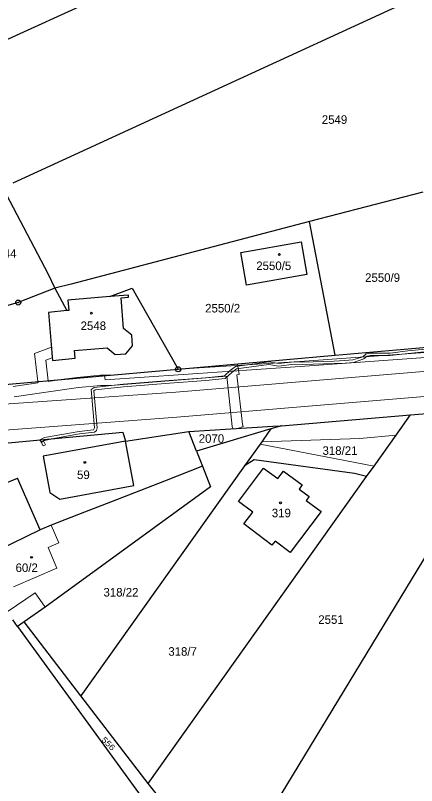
# Model space of a CAD drawing. Extents: x -606517 to -602431, y -1183120 to -1179397.
# Drawn here: x -605212.1 to -605132.4, y -1181010.4 to -1180857.3 of the extents above; entities that cross this region are included whole.
import ezdxf
from ezdxf.enums import TextEntityAlignment as Align

# ---------------------------------------------------------------- set-up
doc = ezdxf.new("R2010")
doc.units = 0
doc.header["$LTSCALE"] = 0.68
for name, color, linetype, lineweight in [('1', 7, 'Continuous', 25), ('13', 7, 'Continuous', 13), ('4', 7, 'Continuous', 13), ('5', 7, 'Continuous', 25), ('8', 7, 'Continuous', 25)]:
    doc.layers.add(name, color=color, linetype=linetype, lineweight=lineweight)
doc.layers.add('2', color=7, linetype='Continuous')

msp = doc.modelspace()

# ---------------------------------------------------------------- linework, layer by layer
at = {"layer": '1'}
for p, q in [((-605226.86, -1180868.06), (-605115.13, -1180816.68)), ((-605212.57, -1180890.57), (-605101.48, -1180839.48)), ((-605214.61, -1180891.56), (-605205.72, -1180908.62)), ((-605131.18, -1180892.4), (-605153.68, -1180898.29)), ((-605153.68, -1180898.29), (-605201.05, -1180910.69)), ((-605148.55, -1180924.86), (-605153.68, -1180898.29)), ((-605167.33, -1180904.4), (-605155.36, -1180902.31)), ((-605155.36, -1180902.31), (-605154.22, -1180908.81)), ((-605166.2, -1180910.91), (-605167.33, -1180904.4)), ((-605205.72, -1180908.62), (-605204.32, -1180911.54)), ((-605154.22, -1180908.81), (-605166.2, -1180910.91)), ((-605204.32, -1180911.54), (-605211.57, -1180914.37)), ((-605201.05, -1180910.69), (-605204.32, -1180911.54)), ((-605204.32, -1180911.54), (-605201.94, -1180915.98)), ((-605193.36, -1180913.2), (-605188.96, -1180911.53)), ((-605188.96, -1180911.53), (-605179.81, -1180927.64)), ((-605193.36, -1180913.2), (-605201.72, -1180913.89)), ((-605189.68, -1180912.89), (-605193.36, -1180913.2)), ((-605191.14, -1180913.46), (-605189.64, -1180913.33)), ((-605189.64, -1180913.33), (-605189.68, -1180912.89)), ((-605211.57, -1180914.37), (-605221.79, -1180917.3)), ((-605201.72, -1180913.89), (-605201.55, -1180915.94)), ((-605190.63, -1180919.53), (-605191.14, -1180913.46)), ((-605201.94, -1180915.98), (-605205.58, -1180916.34)), ((-605205.58, -1180916.34), (-605204.76, -1180925.9)), ((-605201.55, -1180915.94), (-605201.94, -1180915.98)), ((-605189.01, -1180920.85), (-605190.63, -1180919.53)), ((-605188.84, -1180922.97), (-605189.01, -1180920.85)), ((-605200.41, -1180923.92), (-605193.9, -1180923.39)), ((-605200.29, -1180925.46), (-605200.41, -1180923.92)), ((-605193.9, -1180923.39), (-605192.29, -1180924.72)), ((-605190.21, -1180924.54), (-605188.84, -1180922.97)), ((-605148.55, -1180924.86), (-605124.32, -1180922.7)), ((-605204.76, -1180925.9), (-605200.29, -1180925.46)), ((-605192.29, -1180924.72), (-605190.21, -1180924.54)), ((-605179.81, -1180927.64), (-605148.55, -1180924.86)), ((-605226.72, -1180931.78), (-605179.81, -1180927.64)), ((-605133.61, -1180936.72), (-605112.56, -1180934.97)), ((-605159.22, -1180938.85), (-605133.61, -1180936.72)), ((-605136.46, -1180940.72), (-605133.61, -1180936.72)), ((-605177.65, -1180940.02), (-605160.98, -1180938.96)), ((-605159.22, -1180938.85), (-605161.36, -1180939.5)), ((-605160.98, -1180938.96), (-605159.22, -1180938.85)), ((-605228.62, -1180943.64), (-605190.82, -1180940.16)), ((-605190.82, -1180940.16), (-605190.27, -1180941.9)), ((-605190.27, -1180941.9), (-605177.65, -1180940.02)), ((-605176.13, -1180943.95), (-605177.65, -1180940.02)), ((-605161.36, -1180939.5), (-605176.13, -1180943.95)), ((-605161.89, -1180940.23), (-605163.17, -1180942.04)), ((-605161.36, -1180939.5), (-605161.89, -1180940.23)), ((-605140.84, -1180946.88), (-605136.46, -1180940.72)), ((-605190.27, -1180941.9), (-605206.62, -1180944.94)), ((-605163.5, -1180942.5), (-605166.58, -1180946.83)), ((-605163.17, -1180942.04), (-605163.5, -1180942.5)), ((-605176.13, -1180943.95), (-605174.98, -1180946.91)), ((-605166.58, -1180946.83), (-605199.13, -1180992.55)), ((-605174.98, -1180946.91), (-605182.52, -1180949.87)), ((-605174.98, -1180946.91), (-605173.38, -1180951.02)), ((-605164.7, -1180945.67), (-605166.58, -1180946.83)), ((-605144.74, -1180948.36), (-605164.7, -1180945.67)), ((-605142.34, -1180948.98), (-605140.84, -1180946.88)), ((-605167.8, -1180953.9), (-605162.8, -1180947.3)), ((-605162.8, -1180947.3), (-605159.99, -1180949.35)), ((-605159.99, -1180949.35), (-605158.84, -1180947.87)), ((-605158.84, -1180947.87), (-605155.13, -1180950.61)), ((-605142.34, -1180948.98), (-605144.74, -1180948.36)), ((-605221.47, -1180953.43), (-605211.76, -1180949.26)), ((-605207.23, -1180959.55), (-605211.76, -1180949.26)), ((-605182.52, -1180949.87), (-605193.25, -1180954.05)), ((-605185.78, -1181010.01), (-605142.34, -1180948.98)), ((-605173.38, -1180951.02), (-605206.24, -1180974.94)), ((-605155.13, -1180950.61), (-605155.76, -1180951.46)), ((-605155.76, -1180951.46), (-605153.75, -1180952.94)), ((-605153.75, -1180952.94), (-605154.32, -1180953.71)), ((-605193.25, -1180954.05), (-605198.4, -1180956.04)), ((-605164.97, -1180956.02), (-605167.8, -1180953.9)), ((-605154.32, -1180953.71), (-605151.38, -1180955.91)), ((-605198.4, -1180956.04), (-605205.06, -1180958.6)), ((-605166.74, -1180958.37), (-605164.97, -1180956.02)), ((-605151.38, -1180955.91), (-605157.55, -1180964.07)), ((-605205.06, -1180958.6), (-605207.23, -1180959.55)), ((-605161.15, -1180962.6), (-605166.74, -1180958.37)), ((-605207.23, -1180959.55), (-605219.08, -1180965.25)), ((-605128.32, -1180960.97), (-605169.43, -1181028.73)), ((-605160.54, -1180961.8), (-605161.15, -1180962.6)), ((-605157.55, -1180964.07), (-605160.54, -1180961.8)), ((-605206.24, -1180974.94), (-605210.4, -1180977.82)), ((-605211.73, -1180978.74), (-605212.65, -1180977.43)), ((-605210.4, -1180977.82), (-605211.73, -1180978.74)), ((-605211.73, -1180978.74), (-605178.4, -1181024.58)), ((-605199.13, -1180992.55), (-605210.4, -1180977.82)), ((-605185.78, -1181010.01), (-605199.13, -1180992.55)), ((-605175.11, -1181023.02), (-605185.78, -1181010.01))]:
    msp.add_line(p, q, dxfattribs=at)
for points in [[(-605203.31, -1180953.46), (-605188.63, -1180950.73), (-605190.27, -1180941.9)], [(-605206.62, -1180944.94), (-605205.27, -1180952.13), (-605203.31, -1180953.46)]]:
    msp.add_lwpolyline(points, dxfattribs=at)
at = {"layer": '13'}
for points in [[(-604998.29, -1180914.05), (-605009.54, -1180914.93), (-605061.31, -1180919), (-605075.44, -1180920.3), (-605155.59, -1180926.08), (-605179.81, -1180927.64), (-605194.41, -1180928.93), (-605194.33, -1180929.71), (-605155.53, -1180927.08), (-605075.34, -1180921.3), (-605061.23, -1180920), (-605055.93, -1180919.13), (-605009.47, -1180915.93), (-604998.24, -1180915.05)], [(-605127.73, -1180923.35), (-605134.14, -1180923.99), (-605137.66, -1180924.43), (-605141.62, -1180924.43), (-605142.41, -1180924.59), (-605143.09, -1180925.14), (-605144.14, -1180925.5), (-605145.07, -1180925.78), (-605146.63, -1180925.91), (-605148.8, -1180926.01), (-605154.99, -1180926.22), (-605156.74, -1180926.14), (-605159.81, -1180926.49), (-605161.77, -1180926.17), (-605168.38, -1180927.09), (-605169.47, -1180927.89), (-605170.61, -1180928.94), (-605174.35, -1180929.34), (-605181.58, -1180929.88), (-605190.71, -1180930.63), (-605196.48, -1180931.24), (-605197.09, -1180931.67), (-605196.42, -1180939.25), (-605196.64, -1180939.68), (-605199.5, -1180940), (-605206.37, -1180941.2), (-605207.27, -1180941.67), (-605204.92, -1180941.46), (-605199.42, -1180940.5), (-605196.42, -1180940.16), (-605196.03, -1180939.79), (-605195.92, -1180939.29), (-605196.57, -1180931.91), (-605196.26, -1180931.72), (-605190.67, -1180931.13), (-605181.54, -1180930.38), (-605174.31, -1180929.84), (-605170.45, -1180929.47), (-605169.15, -1180928.27), (-605168.18, -1180927.57), (-605161.77, -1180926.67), (-605159.83, -1180926.99), (-605156.72, -1180926.64), (-605154.99, -1180926.72), (-605148.78, -1180926.51), (-605146.59, -1180926.41), (-605144.97, -1180926.28), (-605143.98, -1180925.98), (-605142.85, -1180925.58), (-605142.19, -1180925.05), (-605141.58, -1180924.93), (-605137.62, -1180924.93), (-605134.08, -1180924.49), (-605127.69, -1180923.85)], [(-605212.4, -1180933.11), (-605206.5, -1180932.25), (-605199.63, -1180931.29), (-605195.16, -1180930.84), (-605193.09, -1180930.86), (-605170.11, -1180929.01), (-605169.03, -1180938.99), (-605168.87, -1180939.46), (-605167.99, -1180939.41), (-605166.87, -1180939.02), (-605167.03, -1180938.55), (-605168.1, -1180928.74), (-605167.64, -1180928.65), (-605168.02, -1180926.59), (-605179.81, -1180927.64), (-605193.17, -1180928.82), (-605194.41, -1180928.93), (-605203.07, -1180929.69), (-605205.65, -1180930.05), (-605205.66, -1180929.92), (-605207.69, -1180930.1), (-605207.66, -1180930.34), (-605212.6, -1180931.05)]]:
    msp.add_lwpolyline(points, dxfattribs=at)
for points in [[(-605206.12, -1180925.85), (-605204.81, -1180925.35), (-605204.99, -1180923.23), (-605208.32, -1180924.51), (-605207.69, -1180930.1), (-605205.66, -1180929.92)], [(-605203.07, -1180929.69), (-605194.41, -1180928.93), (-605193.17, -1180928.82), (-605195.26, -1180928.78), (-605199.87, -1180929.25)], [(-605207.27, -1180941.67), (-605206.63, -1180942.86), (-605206.18, -1180942.65), (-605206.53, -1180941.89), (-605204.92, -1180941.46)], [(-605207.06, -1180941.65), (-605207.2, -1180941.81), (-605206.84, -1180942.15), (-605206.36, -1180941.59)]]:
    msp.add_lwpolyline(points, close=True, dxfattribs=at)
at = {"layer": '4'}
for p, q in [((-605143.68, -1180941.43), (-605136.46, -1180940.72)), ((-605163.5, -1180942.5), (-605140.84, -1180946.88)), ((-605143.68, -1180941.43), (-605163.17, -1180942.04)), ((-605203.5, -1180962.17), (-605205.06, -1180958.6)), ((-605205.66, -1180963.09), (-605203.5, -1180962.17)), ((-605203.89, -1180967.2), (-605205.66, -1180963.09)), ((-605212.52, -1180970.91), (-605203.89, -1180967.2)), ((-605213.76, -1180975.83), (-605208.22, -1180972.07)), ((-605208.22, -1180972.07), (-605206.24, -1180974.94))]:
    msp.add_line(p, q, dxfattribs=at)
for points in [[(-605019.1, -1180918.73), (-605180.25, -1180932.22), (-605225.75, -1180935.39), (-605261.87, -1180939.25), (-605283.98, -1180945.35), (-605296.94, -1180949.14)], [(-605262.69, -1180946.11), (-605224.79, -1180940.54), (-605180.08, -1180937.13), (-605018.93, -1180923.69), (-604991.13, -1180921.45)]]:
    msp.add_lwpolyline(points, dxfattribs=at)
at = {"layer": '5'}
for centre in [(-605159.6768, -1180904.8292), (-605197.0568, -1180916.4792), (-605198.3268, -1180946.1492), (-605159.4468, -1180954.1892), (-605208.9268, -1180965.0192)]:
    msp.add_circle(centre, 0.175, dxfattribs=at)
at = {"layer": '8'}
for centre, radius in [((-605211.57, -1180914.3699), 0.5), ((-605211.57, -1180914.3699), 0.0303), ((-605179.81, -1180927.6399), 0.5), ((-605179.81, -1180927.6399), 0.0303)]:
    msp.add_circle(centre, radius, dxfattribs=at)

# ---------------------------------------------------------------- texts
at = {"layer": '2'}
for s, p in [('2549', (-605151.24, -1180878.845)), ('2544', (-605216.98, -1180905.465)), ('2548', (-605199.18, -1180919.835)), ('2070', (-605175.71, -1180942.255)), ('318/21', (-605151.1, -1180944.655)), ('319', (-605161.18, -1180957.055)), ('60/2', (-605212.11, -1180967.945)), ('318/22', (-605194.64, -1180972.815)), ('2551', (-605151.94, -1180978.245)), ('318/7', (-605181.75, -1180984.585))]:
    msp.add_text(s, height=1.7, dxfattribs=at).set_placement(p)
for s, p in [('2550/5', (-605160.79, -1180907.915)), ('2550/9', (-605139.16, -1180910.262)), ('2550/2', (-605170.95, -1180916.345)), ('59', (-605198.629, -1180949.465))]:
    msp.add_text(s, height=1.7, dxfattribs=at).set_placement(p, align=Align.CENTER)
at = {"layer": '2', "width": 1.2}
msp.add_text('556', height=1.14, rotation=315, dxfattribs=at).set_placement((-605194.0621, -1181002.4629), align=Align.CENTER)

doc.saveas('drawing.dxf')
